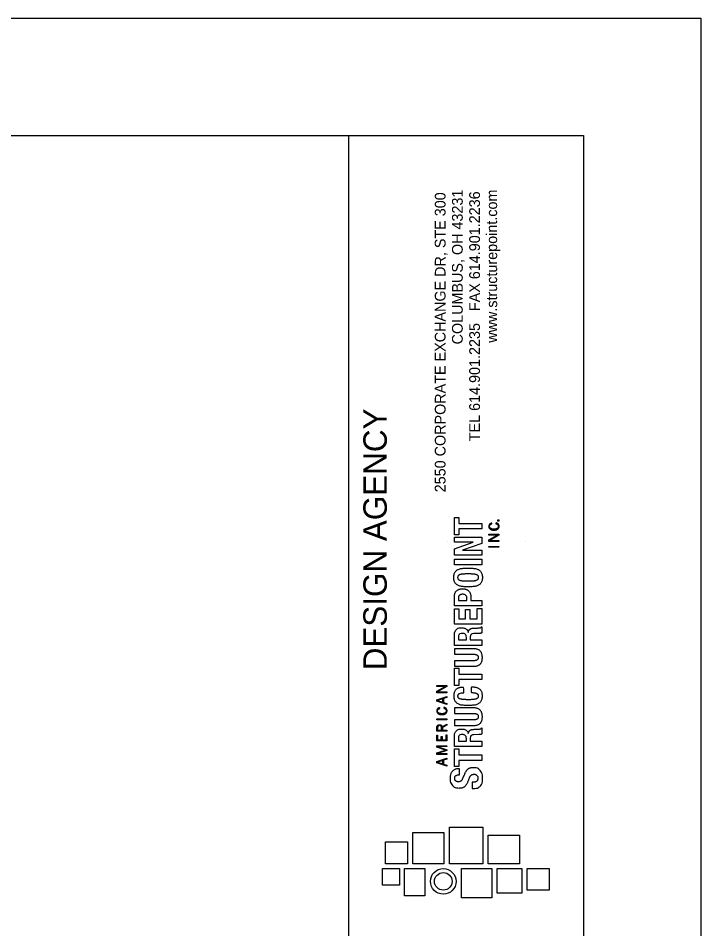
# Model space of a CAD drawing. Extents: x 7.2 to 41.2, y -3.5 to 18.5.
# Drawn here: x 38.254 to 41.162, y 14.607 to 18.483 of the extents above; entities that cross this region are included whole.
import ezdxf

# ---------------------------------------------------------------- set-up
doc = ezdxf.new("R2010")
doc.units = 0
for name, color, linetype in [('Default', 7, 'Continuous'), ('SH_Border', 7, 'Continuous'), ('SH_Cut_Line', 7, 'Continuous'), ('SH_Data', 7, 'Continuous')]:
    doc.layers.add(name, color=color, linetype=linetype)

msp = doc.modelspace()

# ---------------------------------------------------------------- linework, layer by layer
at = {"layer": 'Default'}
for points in [[(40.1123, 16.3579), (40.1316, 16.3579), (40.1316, 16.3323), (40.229, 16.3323), (40.229, 16.3089), (40.1316, 16.3089), (40.1316, 16.2834), (40.1123, 16.2834), (40.1123, 16.3579)], [(40.3018, 16.3426), (40.2965, 16.3426), (40.2965, 16.3476), (40.3018, 16.3476), (40.3018, 16.3426)], [(40.2593, 16.2555), (40.2593, 16.262), (40.2947, 16.2823), (40.2947, 16.2824), (40.2593, 16.2824), (40.2593, 16.2863), (40.3018, 16.2863), (40.3018, 16.2823), (40.2625, 16.2595), (40.2625, 16.2594), (40.3018, 16.2594), (40.3018, 16.2555), (40.2593, 16.2555)], [(40.1123, 16.2236), (40.1922, 16.252), (40.1922, 16.2523), (40.1123, 16.2523), (40.1123, 16.2739), (40.229, 16.2739), (40.229, 16.2471), (40.1472, 16.2183), (40.1472, 16.218), (40.229, 16.218), (40.229, 16.1965), (40.1123, 16.1965), (40.1123, 16.2236)], [(40.2593, 16.2307), (40.2593, 16.2346), (40.3018, 16.2346), (40.3018, 16.2307), (40.2593, 16.2307)], [(40.229, 16.1562), (40.1123, 16.1562), (40.1123, 16.1796), (40.229, 16.1796), (40.229, 16.1562)], [(40.229, 15.9809), (40.1123, 15.9809), (40.1123, 16.022)], [(40.1297, 16.0043), (40.1649, 16.0043), (40.1649, 16.0148)], [(40.1297, 16.0141), (40.1297, 16.0043)], [(40.1823, 16.0169), (40.1823, 16.0043), (40.229, 16.0043), (40.229, 15.9809)], [(40.1123, 15.9682), (40.1316, 15.9682), (40.1316, 15.9264), (40.1589, 15.9264), (40.1589, 15.9657), (40.1782, 15.9657), (40.1782, 15.9264), (40.2096, 15.9264), (40.2096, 15.9698), (40.229, 15.9698), (40.229, 15.903), (40.1123, 15.903), (40.1123, 15.9682)], [(40.229, 15.8129), (40.1123, 15.8129), (40.1123, 15.8564)], [(40.1711, 15.8682), (40.1714, 15.8682)], [(40.2167, 15.8638), (40.1943, 15.8632)], [(40.228, 15.8922), (40.229, 15.8922), (40.229, 15.8668)], [(40.1297, 15.8476), (40.1297, 15.8363)], [(40.1297, 15.8363), (40.1632, 15.8363), (40.1632, 15.8462)], [(40.1796, 15.8491), (40.1796, 15.8363), (40.229, 15.8363), (40.229, 15.8129)], [(40.1123, 15.7163), (40.1316, 15.7163), (40.1316, 15.6908), (40.229, 15.6908), (40.229, 15.6673), (40.1316, 15.6673), (40.1316, 15.6418), (40.1123, 15.6418), (40.1123, 15.7163)], [(40.0375, 15.611), (40.0375, 15.6176), (40.073, 15.6378), (40.073, 15.638), (40.0375, 15.638), (40.0375, 15.6418), (40.0801, 15.6418), (40.0801, 15.6378), (40.0407, 15.615), (40.0407, 15.6149), (40.0801, 15.6149), (40.0801, 15.611), (40.0375, 15.611)], [(40.0801, 15.5618), (40.0375, 15.5754), (40.0375, 15.5814), (40.0801, 15.5948), (40.0801, 15.5907), (40.0662, 15.5864), (40.0662, 15.5703), (40.0801, 15.5659), (40.0801, 15.5618)], [(40.063, 15.5713), (40.063, 15.5855), (40.0407, 15.5784), (40.0407, 15.5783), (40.063, 15.5713)], [(40.0375, 15.4966), (40.0375, 15.5005), (40.0801, 15.5005), (40.0801, 15.4966), (40.0375, 15.4966)], [(40.0599, 15.4667), (40.0801, 15.4771), (40.0801, 15.4729), (40.0607, 15.463), (40.0607, 15.452), (40.0801, 15.452), (40.0801, 15.4481), (40.0375, 15.4481), (40.0375, 15.4625)], [(40.0801, 15.4065), (40.0375, 15.4065), (40.0375, 15.4308), (40.0407, 15.4308), (40.0407, 15.4104), (40.0564, 15.4104), (40.0564, 15.4251), (40.0596, 15.4251), (40.0596, 15.4104), (40.0769, 15.4104), (40.0769, 15.4319), (40.0801, 15.4319), (40.0801, 15.4065)], [(40.0407, 15.452), (40.0574, 15.452), (40.0574, 15.4625)], [(40.0407, 15.4625), (40.0407, 15.452)], [(40.1711, 15.4373), (40.1714, 15.4373)], [(40.2167, 15.433), (40.1943, 15.4323)], [(40.228, 15.4614), (40.229, 15.4614), (40.229, 15.4359)], [(40.229, 15.382), (40.1123, 15.382), (40.1123, 15.4256)], [(40.1297, 15.4167), (40.1297, 15.4054)], [(40.1297, 15.4054), (40.1632, 15.4054), (40.1632, 15.4154)], [(40.1796, 15.4182), (40.1796, 15.4054), (40.229, 15.4054), (40.229, 15.382)], [(40.0801, 15.3486), (40.0375, 15.3486), (40.0375, 15.3555), (40.0736, 15.3672), (40.0736, 15.3673), (40.0375, 15.3791), (40.0375, 15.386), (40.0801, 15.386), (40.0801, 15.3821), (40.0407, 15.3821), (40.0407, 15.3819), (40.0801, 15.3691), (40.0801, 15.3654), (40.0407, 15.3526), (40.0407, 15.3525), (40.0801, 15.3525), (40.0801, 15.3486)], [(40.1123, 15.3726), (40.1316, 15.3726), (40.1316, 15.3471), (40.229, 15.3471), (40.229, 15.3236), (40.1316, 15.3236), (40.1316, 15.2981), (40.1123, 15.2981), (40.1123, 15.3726)], [(40.0801, 15.2994), (40.0375, 15.313), (40.0375, 15.319), (40.0801, 15.3324), (40.0801, 15.3283), (40.0662, 15.324), (40.0662, 15.3079), (40.0801, 15.3035), (40.0801, 15.2994)], [(40.063, 15.3089), (40.063, 15.3231), (40.0407, 15.316), (40.0407, 15.3159), (40.063, 15.3089)]]:
    msp.add_lwpolyline(points, dxfattribs=at)
for points in [[(39.935, 14.8837), (39.935, 15.0163), (40.0676, 15.0163), (40.0676, 14.8837)], [(40.0908, 14.8837), (40.0908, 15.0392), (40.2334, 15.0392), (40.2334, 14.8837)], [(40.2566, 14.8837), (40.2566, 15.0052), (40.3892, 15.0052), (40.3892, 14.8837)], [(39.8192, 14.8837), (39.8192, 14.9763), (39.9118, 14.9763), (39.9118, 14.8837)], [(39.8064, 14.7916), (39.8064, 14.8629), (39.8777, 14.8629), (39.8777, 14.7916)], [(39.8993, 14.747), (39.8993, 14.8629), (39.9866, 14.8629), (39.9866, 14.747)], [(40.143, 14.7386), (40.143, 14.8629), (40.2713, 14.8629), (40.2713, 14.7386)], [(40.294, 14.7577), (40.294, 14.8629), (40.3992, 14.8629), (40.3992, 14.7577)], [(40.4227, 14.7703), (40.4227, 14.8629), (40.5154, 14.8629), (40.5154, 14.7703)]]:
    msp.add_lwpolyline(points, close=True, dxfattribs=at)
for radius in [0.0545, 0.0374]:
    msp.add_circle((40.0646, 14.8083), radius, dxfattribs=at)
for points in [[(40.2718, 16.3301), (40.2686, 16.3292), (40.2662, 16.3279), (40.2645, 16.3262), (40.2628, 16.3245), (40.2619, 16.3224), (40.2619, 16.3198), (40.2619, 16.3177), (40.2624, 16.3158), (40.2634, 16.3143), (40.2643, 16.3128), (40.2657, 16.3116), (40.2673, 16.3106), (40.269, 16.3096), (40.271, 16.3088), (40.2733, 16.3084), (40.2756, 16.3079), (40.278, 16.3076), (40.2806, 16.3076), (40.2832, 16.3076), (40.2856, 16.3079), (40.2879, 16.3084), (40.2902, 16.3088), (40.2921, 16.3096), (40.2938, 16.3106), (40.2955, 16.3116), (40.2968, 16.3129), (40.2978, 16.3145), (40.2987, 16.3161), (40.2992, 16.318), (40.2992, 16.3202), (40.2992, 16.3219), (40.2989, 16.3233), (40.2984, 16.3245), (40.2978, 16.3257), (40.297, 16.3267), (40.2961, 16.3276), (40.2952, 16.3284), (40.2941, 16.3291), (40.2928, 16.3296), (40.2915, 16.3301), (40.2902, 16.3306), (40.2889, 16.3309), (40.2889, 16.3309), (40.2895, 16.3346), (40.2895, 16.3346), (40.2914, 16.3342), (40.2931, 16.3336), (40.2947, 16.3329), (40.2963, 16.3322), (40.2977, 16.3312), (40.2988, 16.3301), (40.3, 16.3289), (40.3008, 16.3276), (40.3015, 16.3259), (40.3021, 16.3243), (40.3024, 16.3224), (40.3024, 16.3201), (40.3024, 16.3175), (40.3019, 16.3152), (40.3009, 16.3132), (40.2998, 16.3112), (40.2983, 16.3095), (40.2964, 16.3081), (40.2945, 16.3067), (40.2922, 16.3056), (40.2895, 16.3049), (40.2869, 16.3041), (40.2839, 16.3038), (40.2806, 16.3038), (40.2773, 16.3038), (40.2743, 16.3041), (40.2716, 16.3049), (40.269, 16.3056), (40.2667, 16.3067), (40.2647, 16.3081), (40.2628, 16.3095), (40.2613, 16.3112), (40.2603, 16.3132), (40.2593, 16.3152), (40.2587, 16.3175), (40.2587, 16.3201), (40.2587, 16.322), (40.259, 16.3237), (40.2597, 16.3252), (40.2603, 16.3267), (40.2612, 16.328), (40.2623, 16.3291), (40.2634, 16.3302), (40.2647, 16.3312), (40.2662, 16.3319), (40.2677, 16.3327), (40.2693, 16.3333), (40.271, 16.3337), (40.271, 16.3337), (40.2718, 16.3301), (40.2718, 16.3301)], [(40.1705, 16.0625), (40.1616, 16.0625), (40.1535, 16.0629), (40.146, 16.0637), (40.1386, 16.0645), (40.1322, 16.0663), (40.1268, 16.0691), (40.1215, 16.0719), (40.1173, 16.0759), (40.1143, 16.0812), (40.1113, 16.0864), (40.1098, 16.0934), (40.1098, 16.1023), (40.1098, 16.1111), (40.1113, 16.1182), (40.1143, 16.1234), (40.1173, 16.1287), (40.1215, 16.1327), (40.1268, 16.1355), (40.1322, 16.1382), (40.1386, 16.14), (40.146, 16.1409), (40.1535, 16.1417), (40.1616, 16.1421), (40.1705, 16.1421), (40.1753, 16.1421), (40.1799, 16.142), (40.1844, 16.1417)], [(40.1844, 16.1417), (40.188, 16.1415), (40.1915, 16.1412), (40.1949, 16.1409), (40.2024, 16.14), (40.2088, 16.1382), (40.2141, 16.1355), (40.2195, 16.1327), (40.2236, 16.1287), (40.2266, 16.1234), (40.2296, 16.1182), (40.2311, 16.1111), (40.2311, 16.1023), (40.2311, 16.0934), (40.2296, 16.0864), (40.2266, 16.0812), (40.2236, 16.0759), (40.2195, 16.0719), (40.2141, 16.0691), (40.2088, 16.0663), (40.2024, 16.0645), (40.1949, 16.0637), (40.1874, 16.0629), (40.1793, 16.0625), (40.1705, 16.0625)], [(40.1705, 16.0859), (40.1783, 16.0859), (40.185, 16.0861), (40.1904, 16.0865), (40.1959, 16.0869), (40.2004, 16.0877), (40.2038, 16.0888), (40.2072, 16.09), (40.2097, 16.0916), (40.2113, 16.0938), (40.2129, 16.0959), (40.2137, 16.0988), (40.2137, 16.1023), (40.2137, 16.1058), (40.2129, 16.1086), (40.2113, 16.1108), (40.2097, 16.1129), (40.2072, 16.1146), (40.2038, 16.1158), (40.2004, 16.1169), (40.1959, 16.1177), (40.1904, 16.1181), (40.185, 16.1184), (40.1783, 16.1186), (40.1705, 16.1186), (40.1626, 16.1186), (40.156, 16.1184), (40.1506, 16.1181), (40.1451, 16.1177), (40.1407, 16.1169), (40.1372, 16.1158), (40.1337, 16.1146), (40.1312, 16.1129), (40.1296, 16.1108), (40.128, 16.1086), (40.1273, 16.1058), (40.1273, 16.1023), (40.1273, 16.0988), (40.128, 16.0959), (40.1296, 16.0938), (40.1312, 16.0916), (40.1337, 16.09), (40.1372, 16.0888), (40.1407, 16.0877), (40.1451, 16.0869), (40.1506, 16.0865), (40.156, 16.0861), (40.1626, 16.0859), (40.1705, 16.0859)], [(40.1123, 16.022), (40.1123, 16.0279), (40.1133, 16.033), (40.1153, 16.037), (40.1173, 16.0411), (40.1199, 16.0444), (40.1232, 16.0469), (40.1265, 16.0494), (40.1302, 16.0512), (40.1344, 16.0523), (40.1386, 16.0534), (40.1429, 16.0539), (40.1472, 16.0539), (40.1533, 16.0539), (40.1586, 16.053), (40.163, 16.0512), (40.1674, 16.0494), (40.171, 16.0469), (40.1738, 16.0437), (40.1767, 16.0405), (40.1788, 16.0366), (40.1802, 16.032), (40.1816, 16.0275), (40.1823, 16.0224), (40.1823, 16.0169)], [(40.1649, 16.0148), (40.1649, 16.0195), (40.1635, 16.0232), (40.1607, 16.0261), (40.1579, 16.029), (40.1535, 16.0305), (40.1475, 16.0305), (40.1418, 16.0305), (40.1374, 16.0292), (40.1343, 16.0267), (40.1313, 16.0242), (40.1297, 16.02), (40.1297, 16.0141)], [(40.1123, 15.8564), (40.1123, 15.8662), (40.1148, 15.8738), (40.1198, 15.8793), (40.1248, 15.8848), (40.1323, 15.8876), (40.1423, 15.8876), (40.1502, 15.8876), (40.1566, 15.886), (40.1615, 15.8828), (40.1665, 15.8797), (40.1697, 15.8748), (40.1711, 15.8682)], [(40.1632, 15.8462), (40.1632, 15.852), (40.1619, 15.8564), (40.1593, 15.8595), (40.1566, 15.8626), (40.1521, 15.8641), (40.1458, 15.8641), (40.1351, 15.8641), (40.1297, 15.8586), (40.1297, 15.8476)], [(40.1714, 15.8682), (40.172, 15.8722), (40.173, 15.8754), (40.1745, 15.8778), (40.1759, 15.8802), (40.178, 15.8821), (40.1808, 15.8835), (40.1836, 15.8849), (40.1871, 15.8858), (40.1914, 15.8862), (40.1956, 15.8866), (40.2008, 15.8869), (40.2071, 15.887), (40.2133, 15.8871), (40.218, 15.8875), (40.2213, 15.8881), (40.2245, 15.8887), (40.2268, 15.8901), (40.228, 15.8922)], [(40.1943, 15.8632), (40.1897, 15.863), (40.1861, 15.8618), (40.1835, 15.8596), (40.1809, 15.8575), (40.1796, 15.8539), (40.1796, 15.8491)], [(40.229, 15.8668), (40.2273, 15.8656), (40.2254, 15.8648), (40.2233, 15.8645), (40.2212, 15.8642), (40.219, 15.8639), (40.2167, 15.8638)], [(40.1123, 15.7478), (40.1123, 15.7478), (40.1935, 15.7478), (40.1935, 15.7478), (40.1964, 15.7478), (40.1991, 15.7479), (40.2015, 15.7483), (40.204, 15.7487), (40.2061, 15.7494), (40.2079, 15.7505), (40.2097, 15.7515), (40.2111, 15.7529), (40.2121, 15.7547), (40.2132, 15.7565), (40.2137, 15.7588), (40.2137, 15.7615), (40.2137, 15.7643), (40.2132, 15.7665), (40.2121, 15.7683), (40.2111, 15.7701), (40.2097, 15.7715), (40.2079, 15.7726), (40.2061, 15.7736), (40.204, 15.7743), (40.2015, 15.7747), (40.1991, 15.7751), (40.1964, 15.7753), (40.1935, 15.7753), (40.1935, 15.7753), (40.1123, 15.7753), (40.1123, 15.7753), (40.1123, 15.7753), (40.1123, 15.7987), (40.1123, 15.7987), (40.1123, 15.7987), (40.1936, 15.7987), (40.1936, 15.7987), (40.201, 15.7987), (40.2071, 15.7977), (40.212, 15.7956), (40.2168, 15.7936), (40.2206, 15.7908), (40.2235, 15.7873), (40.2263, 15.7838), (40.2283, 15.7799), (40.2294, 15.7754), (40.2306, 15.7709), (40.2311, 15.7663), (40.2311, 15.7615), (40.2311, 15.7567), (40.2306, 15.7521), (40.2297, 15.7476), (40.2287, 15.7432), (40.2268, 15.7392), (40.224, 15.7357), (40.2213, 15.7322), (40.2174, 15.7295), (40.2126, 15.7274), (40.2078, 15.7253), (40.2014, 15.7243), (40.1936, 15.7243), (40.1936, 15.7243), (40.1123, 15.7243), (40.1123, 15.7243), (40.1123, 15.7243), (40.1123, 15.7478), (40.1123, 15.7478)], [(40.1516, 15.6108), (40.1431, 15.6108), (40.1369, 15.6098), (40.1331, 15.6078), (40.1292, 15.6058), (40.1273, 15.6021), (40.1273, 15.5967), (40.1273, 15.5938), (40.128, 15.5913), (40.1296, 15.5894), (40.1312, 15.5875), (40.1338, 15.586), (40.1373, 15.5849), (40.1408, 15.5838), (40.1454, 15.583), (40.1511, 15.5826), (40.1569, 15.5821), (40.1638, 15.5819), (40.1721, 15.5819), (40.1809, 15.5819), (40.188, 15.5822), (40.1935, 15.5828), (40.1989, 15.5834), (40.2031, 15.5844), (40.2061, 15.5856), (40.2091, 15.5869), (40.2111, 15.5885), (40.2121, 15.5904), (40.2132, 15.5923), (40.2137, 15.5946), (40.2137, 15.5971), (40.2137, 15.5992), (40.2133, 15.6011), (40.2126, 15.6029), (40.2119, 15.6048), (40.2105, 15.6063), (40.2084, 15.6076), (40.2062, 15.609), (40.2032, 15.61), (40.1994, 15.6108), (40.1955, 15.6115), (40.1904, 15.6119), (40.1841, 15.6119), (40.1841, 15.6119), (40.1841, 15.6354), (40.1841, 15.6354), (40.1904, 15.6354), (40.1964, 15.6349), (40.2021, 15.6339), (40.2077, 15.6329), (40.2127, 15.6311), (40.2171, 15.6284), (40.2214, 15.6257), (40.2248, 15.622), (40.2273, 15.6171), (40.2299, 15.6123), (40.2311, 15.606), (40.2311, 15.5982), (40.2311, 15.5894), (40.2296, 15.5824), (40.2266, 15.5771), (40.2236, 15.5719), (40.2195, 15.5679), (40.2141, 15.5651), (40.2088, 15.5623), (40.2024, 15.5605), (40.1949, 15.5597), (40.1874, 15.5589), (40.1793, 15.5585), (40.1705, 15.5585), (40.1616, 15.5585), (40.1535, 15.5589), (40.146, 15.5597), (40.1386, 15.5605), (40.1322, 15.5623), (40.1268, 15.5651), (40.1215, 15.5679), (40.1173, 15.5719), (40.1143, 15.5771), (40.1113, 15.5823), (40.1098, 15.5894), (40.1098, 15.5982), (40.1098, 15.6066), (40.1112, 15.6132), (40.1139, 15.618), (40.1167, 15.6229), (40.1202, 15.6265), (40.1244, 15.6289), (40.1286, 15.6313), (40.1331, 15.6328), (40.138, 15.6334), (40.1428, 15.634), (40.1474, 15.6343), (40.1516, 15.6343), (40.1516, 15.6343), (40.1516, 15.6108), (40.1516, 15.6108)], [(40.05, 15.5447), (40.0469, 15.5438), (40.0445, 15.5425), (40.0428, 15.5408), (40.0411, 15.5391), (40.0402, 15.5369), (40.0402, 15.5343), (40.0402, 15.5322), (40.0407, 15.5304), (40.0416, 15.5289), (40.0426, 15.5274), (40.0439, 15.5261), (40.0456, 15.5251), (40.0473, 15.5241), (40.0493, 15.5234), (40.0516, 15.5229), (40.0538, 15.5225), (40.0563, 15.5222), (40.0588, 15.5222), (40.0614, 15.5222), (40.0639, 15.5225), (40.0661, 15.5229), (40.0684, 15.5234), (40.0704, 15.5241), (40.0721, 15.5252), (40.0738, 15.5262), (40.0751, 15.5275), (40.076, 15.5291), (40.077, 15.5307), (40.0775, 15.5326), (40.0775, 15.5348), (40.0775, 15.5364), (40.0772, 15.5379), (40.0766, 15.5391), (40.0761, 15.5403), (40.0753, 15.5413), (40.0744, 15.5421), (40.0734, 15.5429), (40.0723, 15.5436), (40.0711, 15.5442), (40.0698, 15.5447), (40.0685, 15.5451), (40.0671, 15.5455), (40.0671, 15.5455), (40.0678, 15.5491), (40.0678, 15.5491), (40.0697, 15.5487), (40.0714, 15.5482), (40.073, 15.5475), (40.0746, 15.5467), (40.0759, 15.5458), (40.0771, 15.5447), (40.0782, 15.5435), (40.0791, 15.5421), (40.0797, 15.5405), (40.0804, 15.5389), (40.0807, 15.5369), (40.0807, 15.5347), (40.0807, 15.5321), (40.0802, 15.5298), (40.0791, 15.5278), (40.0781, 15.5258), (40.0766, 15.5241), (40.0747, 15.5227), (40.0728, 15.5213), (40.0705, 15.5202), (40.0678, 15.5195), (40.0651, 15.5187), (40.0621, 15.5183), (40.0588, 15.5183), (40.0555, 15.5183), (40.0526, 15.5187), (40.0499, 15.5195), (40.0472, 15.5202), (40.0449, 15.5213), (40.043, 15.5227), (40.0411, 15.5241), (40.0396, 15.5258), (40.0386, 15.5278), (40.0375, 15.5298), (40.037, 15.5321), (40.037, 15.5347), (40.037, 15.5366), (40.0373, 15.5383), (40.0379, 15.5398), (40.0386, 15.5413), (40.0394, 15.5426), (40.0405, 15.5437), (40.0416, 15.5448), (40.0429, 15.5457), (40.0444, 15.5465), (40.0459, 15.5472), (40.0475, 15.5478), (40.0493, 15.5483), (40.0493, 15.5483), (40.05, 15.5447), (40.05, 15.5447)], [(40.1123, 15.4958), (40.1123, 15.4958), (40.1935, 15.4958), (40.1935, 15.4958), (40.1964, 15.4958), (40.1991, 15.496), (40.2015, 15.4964), (40.204, 15.4968), (40.2061, 15.4975), (40.2079, 15.4985), (40.2097, 15.4996), (40.2111, 15.501), (40.2121, 15.5028), (40.2132, 15.5046), (40.2137, 15.5069), (40.2137, 15.5096), (40.2137, 15.5123), (40.2132, 15.5146), (40.2121, 15.5164), (40.2111, 15.5182), (40.2097, 15.5196), (40.2079, 15.5207), (40.2061, 15.5217), (40.204, 15.5224), (40.2015, 15.5228), (40.1991, 15.5232), (40.1964, 15.5234), (40.1935, 15.5234), (40.1935, 15.5234), (40.1123, 15.5234), (40.1123, 15.5234), (40.1123, 15.5234), (40.1123, 15.5468), (40.1123, 15.5468), (40.1123, 15.5468), (40.1936, 15.5468), (40.1936, 15.5468), (40.201, 15.5468), (40.2071, 15.5458), (40.212, 15.5437), (40.2168, 15.5416), (40.2206, 15.5389), (40.2235, 15.5354), (40.2263, 15.5319), (40.2283, 15.5279), (40.2294, 15.5235), (40.2306, 15.519), (40.2311, 15.5144), (40.2311, 15.5096), (40.2311, 15.5048), (40.2306, 15.5002), (40.2297, 15.4957), (40.2287, 15.4913), (40.2268, 15.4873), (40.224, 15.4838), (40.2213, 15.4803), (40.2174, 15.4776), (40.2126, 15.4755), (40.2078, 15.4734), (40.2014, 15.4724), (40.1936, 15.4724), (40.1936, 15.4724), (40.1123, 15.4724), (40.1123, 15.4724), (40.1123, 15.4724), (40.1123, 15.4958), (40.1123, 15.4958)], [(40.0375, 15.4625), (40.0375, 15.4667), (40.0386, 15.4699), (40.0407, 15.4722), (40.0428, 15.4744), (40.0456, 15.4755), (40.0491, 15.4755), (40.0519, 15.4755), (40.0542, 15.4748), (40.056, 15.4734), (40.0579, 15.472), (40.0591, 15.4698), (40.0599, 15.4667)], [(40.0574, 15.4625), (40.0574, 15.4653), (40.0567, 15.4675), (40.0552, 15.4692), (40.0538, 15.4708), (40.0517, 15.4717), (40.0491, 15.4717), (40.0465, 15.4717), (40.0444, 15.4709), (40.043, 15.4694), (40.0415, 15.4678), (40.0407, 15.4655), (40.0407, 15.4625)], [(40.1123, 15.4256), (40.1123, 15.4353), (40.1148, 15.4429), (40.1198, 15.4484), (40.1248, 15.4539), (40.1323, 15.4567), (40.1423, 15.4567), (40.1502, 15.4567), (40.1566, 15.4551), (40.1615, 15.452), (40.1665, 15.4488), (40.1697, 15.4439), (40.1711, 15.4373)], [(40.1632, 15.4154), (40.1632, 15.4211), (40.1619, 15.4255), (40.1593, 15.4286), (40.1566, 15.4317), (40.1521, 15.4332), (40.1458, 15.4332), (40.1351, 15.4332), (40.1297, 15.4277), (40.1297, 15.4167)], [(40.1714, 15.4373), (40.172, 15.4413), (40.173, 15.4446), (40.1745, 15.447), (40.1759, 15.4494), (40.178, 15.4513), (40.1808, 15.4526), (40.1836, 15.454), (40.1871, 15.4549), (40.1914, 15.4553), (40.1956, 15.4558), (40.2008, 15.456), (40.2071, 15.4561), (40.2133, 15.4562), (40.218, 15.4566), (40.2213, 15.4572), (40.2245, 15.4578), (40.2268, 15.4592), (40.228, 15.4614)], [(40.1943, 15.4323), (40.1897, 15.4321), (40.1861, 15.4309), (40.1835, 15.4287), (40.1809, 15.4266), (40.1796, 15.4231), (40.1796, 15.4182)], [(40.229, 15.4359), (40.2273, 15.4347), (40.2254, 15.4339), (40.2233, 15.4336), (40.2212, 15.4333), (40.219, 15.4331), (40.2167, 15.433)], [(40.1878, 15.2307), (40.1878, 15.2307), (40.1917, 15.2307), (40.1917, 15.2307), (40.1947, 15.2307), (40.1976, 15.2309), (40.2001, 15.2314), (40.2026, 15.2319), (40.2048, 15.2328), (40.2065, 15.2342), (40.2082, 15.2356), (40.2096, 15.2374), (40.2106, 15.2396), (40.2116, 15.2418), (40.2121, 15.2447), (40.2121, 15.2483), (40.2121, 15.2524), (40.2107, 15.256), (40.2081, 15.2593), (40.2054, 15.2626), (40.2013, 15.2642), (40.1957, 15.2642), (40.1927, 15.2642), (40.1902, 15.2638), (40.188, 15.263), (40.1858, 15.2622), (40.1839, 15.2609), (40.1822, 15.259), (40.1804, 15.2572), (40.1789, 15.2547), (40.1774, 15.2517), (40.176, 15.2487), (40.1746, 15.245), (40.1731, 15.2405), (40.1711, 15.2346), (40.1689, 15.2295), (40.1665, 15.2251), (40.1641, 15.2208), (40.1613, 15.2172), (40.1582, 15.2143), (40.1551, 15.2114), (40.1515, 15.2093), (40.1475, 15.2079), (40.1434, 15.2066), (40.1385, 15.2059), (40.133, 15.2059), (40.12, 15.2059), (40.1102, 15.2095), (40.1037, 15.2168), (40.0972, 15.2241), (40.094, 15.2341), (40.094, 15.2468), (40.094, 15.2527), (40.0946, 15.2581), (40.0959, 15.2631), (40.0972, 15.2681), (40.0993, 15.2725), (40.1022, 15.2761), (40.1051, 15.2797), (40.1088, 15.2826), (40.1134, 15.2846), (40.1179, 15.2866), (40.1233, 15.2877), (40.1296, 15.2877), (40.1296, 15.2877), (40.1333, 15.2877), (40.1333, 15.2877), (40.1333, 15.2877), (40.1333, 15.262), (40.1333, 15.262), (40.127, 15.262), (40.1221, 15.2609), (40.1187, 15.2587), (40.1153, 15.2565), (40.1136, 15.2528), (40.1136, 15.2477), (40.1136, 15.2447), (40.1141, 15.2423), (40.1149, 15.2403), (40.1158, 15.2384), (40.1169, 15.2368), (40.1184, 15.2356), (40.1198, 15.2345), (40.1214, 15.2337), (40.1233, 15.2332), (40.1251, 15.2328), (40.1271, 15.2326), (40.129, 15.2326), (40.1331, 15.2326), (40.1365, 15.2335), (40.1393, 15.2352), (40.1421, 15.2369), (40.1447, 15.2406), (40.147, 15.2463), (40.147, 15.2463), (40.1559, 15.2669), (40.1559, 15.2669), (40.1582, 15.2718), (40.1605, 15.2759), (40.1629, 15.2792), (40.1653, 15.2824), (40.1679, 15.285), (40.1707, 15.2869), (40.1735, 15.2888), (40.1766, 15.2902), (40.1799, 15.2909), (40.1832, 15.2917), (40.1869, 15.292), (40.191, 15.292), (40.205, 15.292), (40.2153, 15.288), (40.2218, 15.2799), (40.2284, 15.2718), (40.2317, 15.2605), (40.2317, 15.2461), (40.2317, 15.231), (40.2283, 15.2202), (40.2216, 15.2137), (40.2149, 15.2072), (40.2054, 15.204), (40.1931, 15.204), (40.1931, 15.204), (40.1878, 15.204), (40.1878, 15.204), (40.1878, 15.204), (40.1878, 15.2307), (40.1878, 15.2307)]]:
    msp.add_open_spline(points, degree=3, dxfattribs=at)
at = {"layer": 'SH_Border'}
msp.add_line((39.6617, -3.0167), (39.6617, 17.9833), dxfattribs=at)
msp.add_lwpolyline([(9.1617, 17.9833), (40.6617, 17.9833), (40.6617, -3.0167), (9.1617, -3.0167)], close=True, dxfattribs=at)
at = {"layer": 'SH_Cut_Line'}
msp.add_lwpolyline([(7.1617, 18.4833), (41.1617, 18.4833), (41.1617, -3.5167), (7.1617, -3.5167)], close=True, dxfattribs=at)
at = {"layer": 'SH_Data'}
for p, q in [((40.0825, 16.2563), (40.0825, 16.2563)), ((40.4159, 16.2564), (40.4159, 16.2564))]:
    msp.add_line(p, q, dxfattribs=at)

# ---------------------------------------------------------------- texts
at = {"layer": 'Default'}
for s, p in [('2550 CORPORATE EXCHANGE DR, STE 300', (40.0744, 16.4648)), ('COLUMBUS, OH 43231', (40.1476, 17.0945)), ('TEL 614.901.2235   FAX 614.901.2236', (40.2209, 16.6823)), ('www.structurepoint.com', (40.2941, 17.1015))]:
    msp.add_text(s, height=0.045714, rotation=90, dxfattribs=at).set_placement(p)
at = {"layer": 'SH_Data'}
msp.add_text('DESIGN AGENCY', height=0.1, rotation=90, dxfattribs=at).set_placement((39.8242, 15.707))

doc.saveas('drawing.dxf')
